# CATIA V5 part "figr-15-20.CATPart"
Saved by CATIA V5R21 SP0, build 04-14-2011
Part number: Part1
Bounding box of the stored display mesh (mm): x -81.56 to 85.56, y -36.965 to 25.965, z 0 to 42
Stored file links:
  D:\CATIA V5R21 E-RESOURCES\CATIA-V5R21\catia-v5r21-prt\c15-catia-v5r20-prt\c15-catia-v5r21-figr-15-20.CATPart
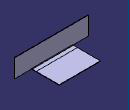
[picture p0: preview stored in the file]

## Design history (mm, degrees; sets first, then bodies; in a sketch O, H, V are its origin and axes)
SheetMetalParameters1: Thickness 1, BendRadius 1, KFactor 0.325257 {= log(min(100,max(20*SheetMetalParameters1.BendRadius,SheetMetalParameters1.Thickness)/SheetMetalParameters1.Thickness))/log(100)/2}, ReliefRadialLength 1, ReliefAxialLength 2, MinimumBendRadius 0
Body1 (main body)
  Sketch1 on xy-plane, origin (0, 0, 0), H (1, 0, 0), V (0, 1, 0)
    line L1 (-46.5596, 25.9646) -> (46.5596, 25.9646)
    line L2 (46.5596, 25.9646) -> (46.5596, -25.9646)
    line L3 (46.5596, -25.9646) -> (-46.5596, -25.9646)
    line L4 (-46.5596, -25.9646) -> (-46.5596, 25.9646)
    horizontal: L1 H, L3 H
    vertical: L2 V, L4 V
    symmetry: L1 L3 H, L4 L2 V
  Wall1: Thickness 1, Profile Sketch1
  d_NewWallOnEdge1: NewWallOnEdge_Edge edge [face of Wall1 | face of Wall1], NewWallOnEdge_Length 42, NewWallOnEdge_HeightLimitOffset 0, NewWallOnEdge_WidthOffset1 39, NewWallOnEdge_WidthOffset2 35, NewWallOnEdge_Angle 90, NewWallOnEdge_BendRadiusValue 1 {= SheetMetalParameters1.BendRadius}, NewWallOnEdge_BendTable SheetMetalParameters1, KFacteur 0.325257 {= log(min(100,max(20*d_NewWallOnEdge1.Radius,SheetMetalParameters1.Thickness)/SheetMetalParameters1.Thickness))/log(100)/2}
